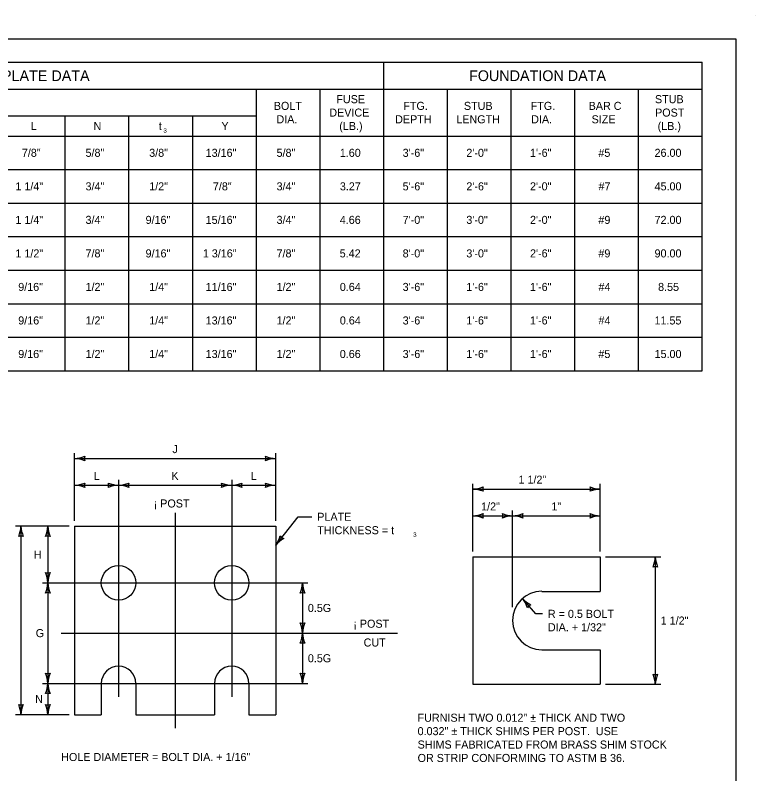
# Model space of a CAD drawing. Extents: x 49991.4 to 50021, y 49987.6 to 50011.4.
# Drawn here: x 50011.38 to 50016.9, y 49993.52 to 49999.18 of the extents above; entities that cross this region are included whole.
import ezdxf

# ---------------------------------------------------------------- set-up
doc = ezdxf.new("R2010")
doc.units = 0
for name, color, linetype in [('Level 1', 7, 'Continuous'), ('Level 2', 7, 'Continuous'), ('Level 3', 7, 'Continuous'), ('Level 5', 7, 'Continuous')]:
    doc.layers.add(name, color=color, linetype=linetype)

msp = doc.modelspace()

# ---------------------------------------------------------------- linework, layer by layer
at = {"layer": 'Level 1'}
for p, q in [((50016.9001, 49999.1756), (50016.9001, 49999.1756)), ((50011.8184, 49995.3646), (50013.3184, 49995.3646)), ((50011.8184, 49995.3646), (50011.8184, 49993.9584)), ((50013.3184, 49995.3646), (50013.3184, 49993.9584)), ((50014.7891, 49995.1367), (50015.7397, 49995.1367)), ((50014.7891, 49995.1367), (50014.7891, 49994.1863)), ((50015.7397, 49995.1367), (50015.7397, 49994.8792)), ((50015.3039, 49994.8792), (50015.7397, 49994.8792)), ((50015.3039, 49994.4438), (50015.7397, 49994.4438)), ((50015.7397, 49994.4438), (50015.7397, 49994.1863)), ((50012.0176, 49994.1928), (50012.0176, 49993.9584)), ((50012.2754, 49994.1928), (50012.2754, 49993.9584)), ((50012.8614, 49994.1928), (50012.8614, 49993.9584)), ((50013.1192, 49994.1928), (50013.1192, 49993.9584)), ((50014.7891, 49994.1863), (50015.7397, 49994.1863)), ((50011.8184, 49993.9584), (50012.0176, 49993.9584)), ((50012.2754, 49993.9584), (50012.8614, 49993.9584)), ((50013.1192, 49993.9584), (50013.3184, 49993.9584))]:
    msp.add_line(p, q, dxfattribs=at)
msp.add_lwpolyline([(49999.3835, 49998.9992), (50016.7501, 49998.9992), (50016.7501, 49987.7988), (49999.3835, 49987.7988)], close=True, dxfattribs=at)
for centre in [(50012.1466, 49994.9428), (50012.9903, 49994.9428)]:
    msp.add_circle(centre, 0.1289, dxfattribs=at)
for centre, radius, start, end in [((50015.3041, 49994.6615), 0.2179, 90, 270), ((50012.1466, 49994.1928), 0.1289, 0, 180), ((50012.9903, 49994.1928), 0.1289, 0, 180)]:
    msp.add_arc(centre, radius, start, end, dxfattribs=at)
at = {"layer": 'Level 2'}
for p, q in [((50002.7742, 49998.8242), (50016.4992, 49998.8242)), ((50014.1242, 49996.5242), (50014.1242, 49998.8242)), ((50016.4992, 49996.5242), (50016.4992, 49998.8242)), ((50002.7742, 49998.6242), (50016.4992, 49998.6242)), ((50013.1742, 49996.5242), (50013.1742, 49998.6242)), ((50013.6492, 49996.5242), (50013.6492, 49998.6242)), ((50014.5992, 49996.5242), (50014.5992, 49998.6242)), ((50015.0742, 49996.5242), (50015.0742, 49998.6242)), ((50015.5492, 49996.5242), (50015.5492, 49998.6242)), ((50016.0242, 49996.5242), (50016.0242, 49998.6242)), ((50008.8992, 49998.4242), (50013.1742, 49998.4242)), ((50011.7492, 49996.5242), (50011.7492, 49998.4242)), ((50012.2242, 49996.5242), (50012.2242, 49998.4242)), ((50012.2242, 49996.5242), (50012.2242, 49998.4242)), ((50012.6992, 49996.5242), (50012.6992, 49998.4242)), ((50002.7742, 49998.2742), (50016.4992, 49998.2742)), ((50004.9742, 49998.0242), (50016.4992, 49998.0242)), ((50002.7742, 49997.7742), (50016.4992, 49997.7742)), ((50004.9742, 49997.5242), (50016.4992, 49997.5242)), ((50002.7742, 49997.2742), (50016.4992, 49997.2742)), ((50004.9742, 49997.0242), (50016.4992, 49997.0242)), ((50002.7742, 49996.7742), (50016.4992, 49996.7742)), ((50002.7742, 49996.5242), (50016.4992, 49996.5242))]:
    msp.add_line(p, q, dxfattribs=at)
at = {"layer": 'Level 3'}
for p, q in [((50011.8184, 49995.4046), (50011.8184, 49995.91)), ((50011.8184, 49995.87), (50013.3184, 49995.87)), ((50013.3184, 49995.4046), (50013.3184, 49995.91)), ((50011.8184, 49995.67), (50012.1466, 49995.67)), ((50012.1466, 49995.67), (50012.9904, 49995.67)), ((50012.9904, 49995.67), (50013.3184, 49995.67)), ((50014.7891, 49995.1767), (50014.7891, 49995.6821)), ((50014.7891, 49995.6421), (50015.7397, 49995.6421)), ((50015.7397, 49995.1767), (50015.7397, 49995.6821)), ((50015.0862, 49994.7615), (50015.0862, 49995.4821)), ((50013.3184, 49995.2237), (50013.487, 49995.4351)), ((50013.487, 49995.4351), (50013.5886, 49995.4351)), ((50014.7891, 49995.4421), (50015.0862, 49995.4421)), ((50015.0862, 49995.4421), (50015.7397, 49995.4421)), ((50011.7784, 49995.3646), (50011.3784, 49995.3646)), ((50011.4184, 49995.3646), (50011.4184, 49993.9584)), ((50011.6184, 49995.3646), (50011.6184, 49994.9428)), ((50015.7797, 49995.1367), (50016.1904, 49995.1367)), ((50016.1504, 49995.1367), (50016.1504, 49994.1863)), ((50011.6184, 49994.9428), (50011.6184, 49994.1928)), ((50013.5184, 49994.9428), (50013.5184, 49994.5678)), ((50015.2598, 49994.7114), (50015.1599, 49994.8248)), ((50015.3091, 49994.7114), (50015.2598, 49994.7114)), ((50013.5184, 49994.5678), (50013.5184, 49994.1928)), ((50011.6184, 49994.1928), (50011.6184, 49993.9584)), ((50015.7797, 49994.1863), (50016.1904, 49994.1863)), ((50011.7784, 49993.9584), (50011.3784, 49993.9584))]:
    msp.add_line(p, q, dxfattribs=at)
for centre, radius, start, end in [((50011.8069, 49996.1027), 0.233, 272.8273, 292.0772), ((50011.8092, 49995.6479), 0.2223, 67.456, 87.6395), ((50011.9466, 49995.87), 0.0548, 162.1388, 197.8612), ((50013.3276, 49996.0921), 0.2223, 247.456, 267.6395), ((50013.1902, 49995.87), 0.0548, 342.1388, 17.8612), ((50013.3299, 49995.6373), 0.233, 92.8273, 112.0772), ((50011.8069, 49995.9027), 0.233, 272.8273, 292.0772), ((50011.8092, 49995.4479), 0.2223, 67.456, 87.6395), ((50011.9466, 49995.67), 0.0548, 162.1388, 197.8612), ((50012.1558, 49995.8921), 0.2223, 247.456, 267.6395), ((50012.0184, 49995.67), 0.0548, 342.1388, 17.8612), ((50012.1581, 49995.4373), 0.233, 92.8273, 112.0772), ((50012.1351, 49995.9027), 0.233, 272.8273, 292.0772), ((50012.1374, 49995.4479), 0.2223, 67.456, 87.6395), ((50012.2748, 49995.67), 0.0548, 162.1388, 197.8612), ((50012.9996, 49995.8921), 0.2223, 247.456, 267.6395), ((50012.8622, 49995.67), 0.0548, 342.1388, 17.8612), ((50013.0019, 49995.4373), 0.233, 92.8273, 112.0772), ((50012.9789, 49995.9027), 0.233, 272.8273, 292.0772), ((50012.9812, 49995.4479), 0.2223, 67.456, 87.6395), ((50013.1186, 49995.67), 0.0548, 162.1388, 197.8612), ((50013.3276, 49995.8921), 0.2223, 247.456, 267.6395), ((50013.1902, 49995.67), 0.0548, 342.1388, 17.8612), ((50013.3299, 49995.4373), 0.233, 92.8273, 112.0772), ((50014.7776, 49995.8748), 0.233, 272.8273, 292.0772), ((50014.7799, 49995.42), 0.2223, 67.456, 87.6395), ((50014.9173, 49995.6421), 0.0548, 162.1388, 197.8612), ((50015.7489, 49995.8642), 0.2223, 247.456, 267.6395), ((50015.6115, 49995.6421), 0.0548, 342.1388, 17.8612), ((50015.7512, 49995.4094), 0.233, 92.8273, 112.0772), ((50014.7776, 49995.6748), 0.233, 272.8273, 292.0772), ((50014.7799, 49995.22), 0.2223, 67.456, 87.6395), ((50014.9173, 49995.4421), 0.0548, 162.1388, 197.8612), ((50015.0954, 49995.6642), 0.2223, 247.456, 267.6395), ((50014.958, 49995.4421), 0.0548, 342.1388, 17.8612), ((50015.0977, 49995.2094), 0.233, 92.8273, 112.0772), ((50015.0747, 49995.6748), 0.233, 272.8273, 292.0772), ((50015.077, 49995.22), 0.2223, 67.456, 87.6395), ((50015.2144, 49995.4421), 0.0548, 162.1388, 197.8612), ((50015.7489, 49995.6642), 0.2223, 247.456, 267.6395), ((50015.6115, 49995.4421), 0.0548, 342.1388, 17.8612), ((50015.7512, 49995.2094), 0.233, 92.8273, 112.0772), ((50011.1963, 49995.3738), 0.2223, 337.456, 357.6395), ((50011.6511, 49995.3761), 0.233, 182.8273, 202.0772), ((50011.3963, 49995.3738), 0.2223, 337.456, 357.6395), ((50011.8511, 49995.3761), 0.233, 182.8273, 202.0772), ((50011.4184, 49995.2364), 0.0548, 72.1388, 107.8612), ((50011.6184, 49995.2364), 0.0548, 72.1388, 107.8612), ((50013.1293, 49995.3598), 0.233, 324.2506, 343.5004), ((50013.4863, 49995.078), 0.2223, 118.8793, 139.0628), ((50013.3983, 49995.3239), 0.0548, 213.5621, 249.2845), ((50015.9283, 49995.1459), 0.2223, 337.456, 357.6395), ((50016.3831, 49995.1482), 0.233, 182.8273, 202.0772), ((50011.6184, 49995.071), 0.0548, 252.1388, 287.8612), ((50011.3857, 49994.9313), 0.233, 2.8273, 22.0772), ((50011.8405, 49994.9336), 0.2223, 157.456, 177.6395), ((50016.1504, 49995.0085), 0.0548, 72.1388, 107.8612), ((50011.3963, 49994.952), 0.2223, 337.456, 357.6395), ((50011.8511, 49994.9543), 0.233, 182.8273, 202.0772), ((50013.2963, 49994.952), 0.2223, 337.456, 357.6395), ((50013.7511, 49994.9543), 0.233, 182.8273, 202.0772), ((50011.6184, 49994.8146), 0.0548, 72.1388, 107.8612), ((50013.5184, 49994.8146), 0.0548, 72.1388, 107.8612), ((50014.9872, 49994.6848), 0.2223, 18.8449, 39.0284), ((50015.3269, 49994.9873), 0.233, 224.2162, 243.466), ((50015.2447, 49994.7286), 0.0548, 113.5277, 149.25), ((50013.5184, 49994.696), 0.0548, 252.1388, 287.8612), ((50013.2857, 49994.5563), 0.233, 2.8273, 22.0772), ((50013.7405, 49994.5586), 0.2223, 157.456, 177.6395), ((50013.2963, 49994.577), 0.2223, 337.456, 357.6395), ((50013.7511, 49994.5793), 0.233, 182.8273, 202.0772), ((50013.5184, 49994.4396), 0.0548, 72.1388, 107.8612), ((50011.6184, 49994.321), 0.0548, 252.1388, 287.8612), ((50011.3857, 49994.1813), 0.233, 2.8273, 22.0772), ((50011.8405, 49994.1836), 0.2223, 157.456, 177.6395), ((50013.5184, 49994.321), 0.0548, 252.1388, 287.8612), ((50013.2857, 49994.1813), 0.233, 2.8273, 22.0772), ((50013.7405, 49994.1836), 0.2223, 157.456, 177.6395), ((50016.1504, 49994.3145), 0.0548, 252.1388, 287.8612), ((50015.9177, 49994.1748), 0.233, 2.8273, 22.0772), ((50016.3725, 49994.1771), 0.2223, 157.456, 177.6395), ((50011.3963, 49994.202), 0.2223, 337.456, 357.6395), ((50011.8511, 49994.2043), 0.233, 182.8273, 202.0772), ((50011.6184, 49994.0646), 0.0548, 72.1388, 107.8612), ((50011.4184, 49994.0866), 0.0548, 252.1388, 287.8612), ((50011.1857, 49993.9469), 0.233, 2.8273, 22.0772), ((50011.6405, 49993.9492), 0.2223, 157.456, 177.6395), ((50011.6184, 49994.0866), 0.0548, 252.1388, 287.8612), ((50011.3857, 49993.9469), 0.233, 2.8273, 22.0772), ((50011.8405, 49993.9492), 0.2223, 157.456, 177.6395)]:
    msp.add_arc(centre, radius, start, end, dxfattribs=at)
at = {"layer": 'Level 5'}
for p, q in [((50012.1466, 49995.71), (50012.1466, 49994.0928)), ((50012.9904, 49995.71), (50012.9904, 49994.0928)), ((50012.5684, 49995.4646), (50012.5684, 49993.8584)), ((50011.5784, 49994.9428), (50013.5584, 49994.9428)), ((50011.7184, 49994.5678), (50014.2276, 49994.5678)), ((50011.5784, 49994.1928), (50013.5584, 49994.1928))]:
    msp.add_line(p, q, dxfattribs=at)

# ---------------------------------------------------------------- texts
at = {"layer": 'Level 2'}
for s, height, p in [('FUSE PLATE DATA', 0.08, (50010.9616, 49998.6842)), ('FOUNDATION DATA', 0.08, (50014.7606, 49998.6842)), ('FUSE', 0.06, (50013.7708, 49998.5192)), ('STUB', 0.06, (50016.1475, 49998.5192)), ('BOLT', 0.06, (50013.3043, 49998.4692)), ('FTG.', 0.06, (50014.2706, 49998.4692)), ('STUB', 0.06, (50014.7225, 49998.4692)), ('FTG.', 0.06, (50015.2206, 49998.4692)), ('BAR C', 0.06, (50015.6529, 49998.4692)), ('DEVICE', 0.06, (50013.7184, 49998.4192)), ('POST', 0.06, (50016.1486, 49998.4192)), ('DIA.', 0.06, (50013.3243, 49998.3692)), ('DEPTH', 0.06, (50014.2094, 49998.3692)), ('LENGTH', 0.06, (50014.6658, 49998.3692)), ('DIA.', 0.06, (50015.2243, 49998.3692)), ('SIZE', 0.06, (50015.6752, 49998.3692)), ('L', 0.06, (50011.4905, 49998.3192)), ('N', 0.06, (50011.9596, 49998.3192)), ('t', 0.06, (50012.4461, 49998.3192)), ('Y', 0.06, (50012.9139, 49998.3192)), ('(LB.)', 0.06, (50013.7929, 49998.3192)), ('(LB.)', 0.06, (50016.1679, 49998.3192)), ('3', 0.0325, (50012.4815, 49998.3)), ('7/8"', 0.06, (50011.425, 49998.1192)), ('5/8"', 0.06, (50011.9, 49998.1192)), ('3/8"', 0.06, (50012.375, 49998.1192)), ('13/16"', 0.06, (50012.7961, 49998.1192)), ('5/8"', 0.06, (50013.325, 49998.1192)), ('1.60', 0.06, (50013.7967, 49998.1192)), ('3\'-6"', 0.06, (50014.2656, 49998.1192)), ('2\'-0"', 0.06, (50014.7406, 49998.1192)), ('1\'-6"', 0.06, (50015.2156, 49998.1192)), ('#5', 0.06, (50015.7255, 49998.1192)), ('26.00', 0.06, (50016.1447, 49998.1192)), ('1 1/4"', 0.06, (50011.377, 49997.8692)), ('3/4"', 0.06, (50011.9, 49997.8692)), ('1/2"', 0.06, (50012.375, 49997.8692)), ('7/8"', 0.06, (50012.85, 49997.8692)), ('3/4"', 0.06, (50013.325, 49997.8692)), ('3.27', 0.06, (50013.7972, 49997.8692)), ('5\'-6"', 0.06, (50014.2656, 49997.8692)), ('2\'-6"', 0.06, (50014.7406, 49997.8692)), ('2\'-0"', 0.06, (50015.2156, 49997.8692)), ('#7', 0.06, (50015.7266, 49997.8692)), ('45.00', 0.06, (50016.1447, 49997.8692)), ('1 1/4"', 0.06, (50011.377, 49997.6192)), ('3/4"', 0.06, (50011.9, 49997.6192)), ('9/16"', 0.06, (50012.348, 49997.6192)), ('15/16"', 0.06, (50012.7961, 49997.6192)), ('3/4"', 0.06, (50013.325, 49997.6192)), ('4.66', 0.06, (50013.7965, 49997.6192)), ('7\'-0"', 0.06, (50014.2656, 49997.6192)), ('3\'-0"', 0.06, (50014.7406, 49997.6192)), ('2\'-0"', 0.06, (50015.2156, 49997.6192)), ('#9', 0.06, (50015.7259, 49997.6192)), ('72.00', 0.06, (50016.1447, 49997.6192)), ('1 1/2"', 0.06, (50011.377, 49997.3692)), ('7/8"', 0.06, (50011.9, 49997.3692)), ('9/16"', 0.06, (50012.348, 49997.3692)), ('1 3/16"', 0.06, (50012.7751, 49997.3692)), ('7/8"', 0.06, (50013.325, 49997.3692)), ('5.42', 0.06, (50013.7959, 49997.3692)), ('8\'-0"', 0.06, (50014.2656, 49997.3692)), ('3\'-0"', 0.06, (50014.7406, 49997.3692)), ('2\'-6"', 0.06, (50015.2156, 49997.3692)), ('#9', 0.06, (50015.7259, 49997.3692)), ('90.00', 0.06, (50016.1447, 49997.3692)), ('9/16"', 0.06, (50011.398, 49997.1192)), ('1/2"', 0.06, (50011.9, 49997.1192)), ('1/4"', 0.06, (50012.375, 49997.1192)), ('11/16"', 0.06, (50012.7961, 49997.1192)), ('1/2"', 0.06, (50013.325, 49997.1192)), ('0.64', 0.06, (50013.797, 49997.1192)), ('3\'-6"', 0.06, (50014.2656, 49997.1192)), ('1\'-6"', 0.06, (50014.7406, 49997.1192)), ('1\'-6"', 0.06, (50015.2156, 49997.1192)), ('#4', 0.06, (50015.7264, 49997.1192)), ('8.55', 0.06, (50016.1711, 49997.1192)), ('9/16"', 0.06, (50011.398, 49996.8692)), ('1/2"', 0.06, (50011.9, 49996.8692)), ('1/4"', 0.06, (50012.375, 49996.8692)), ('13/16"', 0.06, (50012.7961, 49996.8692)), ('1/2"', 0.06, (50013.325, 49996.8692)), ('0.64', 0.06, (50013.797, 49996.8692)), ('3\'-6"', 0.06, (50014.2656, 49996.8692)), ('1\'-6"', 0.06, (50014.7406, 49996.8692)), ('1\'-6"', 0.06, (50015.2156, 49996.8692)), ('#4', 0.06, (50015.7264, 49996.8692)), ('11.55', 0.06, (50016.1442, 49996.8692)), ('9/16"', 0.06, (50011.398, 49996.6192)), ('1/2"', 0.06, (50011.9, 49996.6192)), ('1/4"', 0.06, (50012.375, 49996.6192)), ('13/16"', 0.06, (50012.7961, 49996.6192)), ('1/2"', 0.06, (50013.325, 49996.6192)), ('0.66', 0.06, (50013.7965, 49996.6192)), ('3\'-6"', 0.06, (50014.2656, 49996.6192)), ('1\'-6"', 0.06, (50014.7406, 49996.6192)), ('1\'-6"', 0.06, (50015.2156, 49996.6192)), ('#5', 0.06, (50015.7255, 49996.6192)), ('15.00', 0.06, (50016.1447, 49996.6192)), ('J', 0.06, (50012.5481, 49995.91)), ('L', 0.06, (50011.9613, 49995.71)), ('K', 0.06, (50012.5404, 49995.71)), ('L', 0.06, (50013.1332, 49995.71)), ('1 1/2"', 0.06, (50015.1297, 49995.6821)), ('¡ POST', 0.06, (50012.4082, 49995.5046)), ('1/2"', 0.06, (50014.8509, 49995.4821)), ('1"', 0.06, (50015.375, 49995.4821)), ('PLATE', 0.06, (50013.6286, 49995.4051)), ('THICKNESS = t', 0.06, (50013.6286, 49995.3051)), ('3', 0.0325, (50014.3443, 49995.2859)), ('H', 0.06, (50011.5144, 49995.1237)), ('0.5G', 0.06, (50013.5584, 49994.7253)), ('R = 0.5 BOLT', 0.06, (50015.3491, 49994.6814)), ('1 1/2"', 0.06, (50016.1904, 49994.6315)), ('¡ POST', 0.06, (50013.8974, 49994.6078)), ('DIA. + 1/32"', 0.06, (50015.3491, 49994.5814)), ('G', 0.06, (50011.5286, 49994.5378)), ('CUT', 0.06, (50013.9743, 49994.4678)), ('0.5G', 0.06, (50013.5584, 49994.3503)), ('N', 0.06, (50011.5241, 49994.0456)), ('FURNISH TWO 0.012" ± THICK AND TWO', 0.06, (50014.3771, 49993.9069)), ('0.032" ± THICK SHIMS PER POST.  USE', 0.06, (50014.3771, 49993.8069)), ('SHIMS FABRICATED FROM BRASS SHIM STOCK', 0.06, (50014.3771, 49993.7069)), ('HOLE DIAMETER = BOLT DIA. + 1/16"', 0.06, (50011.7184, 49993.6141)), ('OR STRIP CONFORMING TO ASTM B 36.', 0.06, (50014.3771, 49993.6069))]:
    msp.add_text(s, height=height, dxfattribs=at).set_placement(p)

doc.saveas('drawing.dxf')
